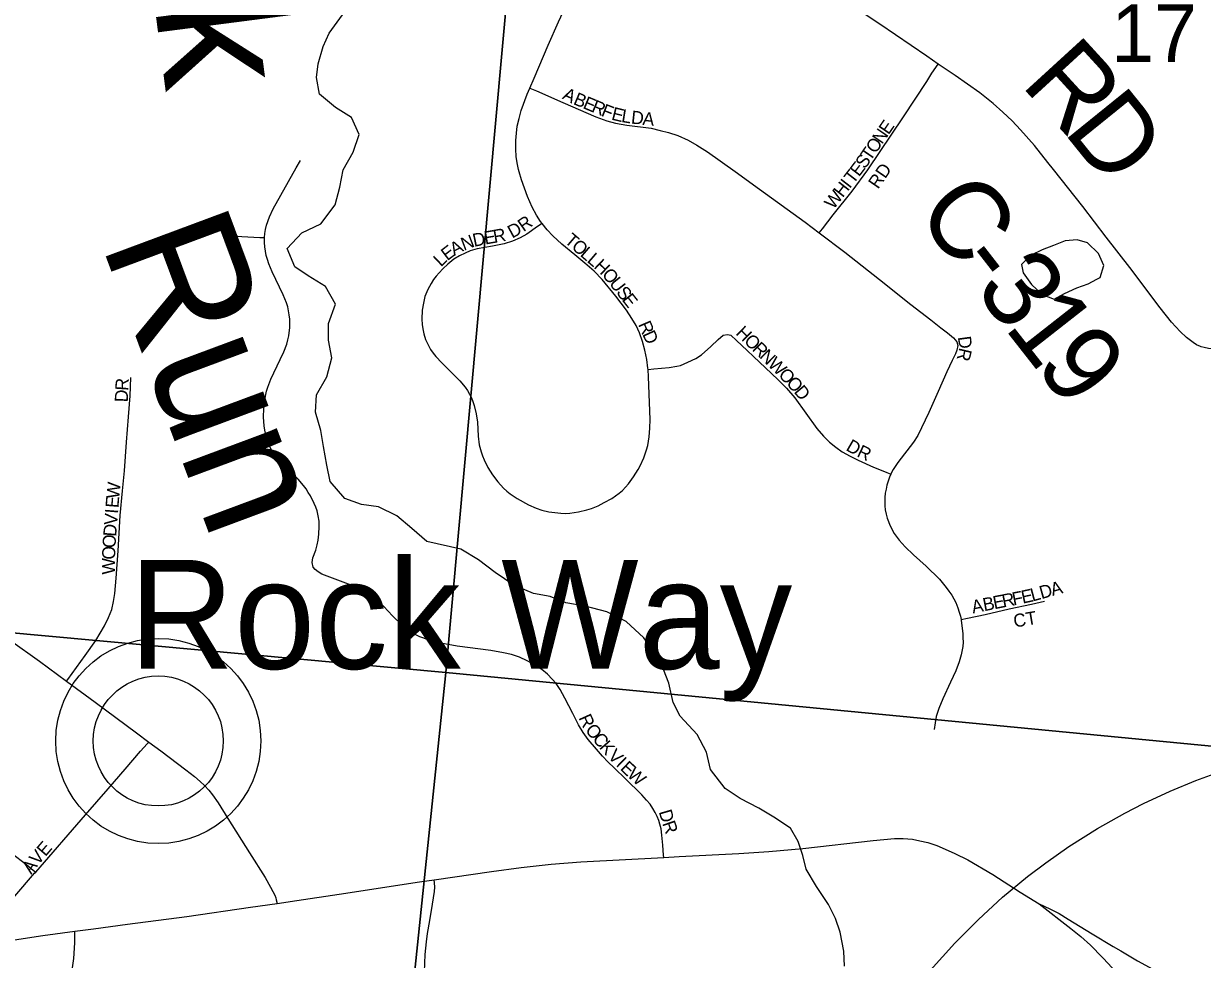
# Model space of a CAD drawing. Extents: x 1410790 to 1770854, y 566777 to 831614.
# Drawn here: x 1581361 to 1585877, y 704158 to 707743 of the extents above; entities that cross this region are included whole.
import ezdxf

# ---------------------------------------------------------------- set-up
doc = ezdxf.new("R2010")
doc.units = 0
for name, color, linetype in [('GM_X_County_Road', 7, 'Continuous'), ('GM_X_County_Road_Text', 7, 'Continuous'), ('GM_X_Minor_Lake', 7, 'Continuous'), ('GM_X_Minor_River', 7, 'Continuous'), ('GM_X_Minor_River_Text', 7, 'Continuous'), ('GM_X_Rail_Line', 7, 'Continuous'), ('GM_X_Section', 7, 'Continuous'), ('GM_X_Section_Text', 7, 'Continuous'), ('GM_X_Township_Road', 7, 'Continuous'), ('GM_X_Township_Subdivision', 7, 'Continuous'), ('GM_X_Township_Subdivision_Text', 7, 'Continuous'), ('GM_X_Unincorporated', 7, 'Continuous'), ('GM_X_Unincorporated_Location', 7, 'Continuous'), ('GM_X_Unincorporated_Text', 7, 'Continuous'), ('GM_X_US_Route', 7, 'Continuous')]:
    doc.layers.add(name, color=color, linetype=linetype)

msp = doc.modelspace()

# ---------------------------------------------------------------- linework, layer by layer
at = {"layer": 'GM_X_County_Road'}
for points in [[(1584864.9, 707588), (1584821.5, 707617.9), (1584640.9, 707741), (1584482.9, 707846.1), (1584384.8, 707911.1), (1584248.4, 707999.9), (1584099.2, 708099.5), (1583987.3, 708174.2), (1583765.5, 708320.1)], [(1585284.6, 707211.2), (1585232.9, 707275.8), (1585180, 707335.6), (1585148.2, 707370), (1585112.5, 707404.2), (1585075.1, 707436.5), (1585023.3, 707477.1), (1584929.6, 707543.5), (1584864.9, 707588)], [(1586504.2, 706606.8), (1586442.1, 706593.4), (1586173, 706537), (1586107.8, 706523.9), (1586043.8, 706510.5), (1585979.6, 706499), (1585947.5, 706496), (1585915.4, 706496.7), (1585899.5, 706498.7), (1585883.8, 706501.7), (1585872.2, 706505.2), (1585868.7, 706506.3), (1585854.4, 706512.6), (1585840.9, 706520.8), (1585815.4, 706540.6), (1585791.7, 706562.8), (1585758.7, 706598.7), (1585714.7, 706654.2), (1585598.5, 706808.4), (1585507.2, 706925), (1585418.7, 707042.2), (1585306.7, 707183.7), (1585284.6, 707211.2)], [(1581204.4, 705424.3), (1581219.9, 705420.6), (1581242.4, 705413.7), (1581264.6, 705404.9), (1581286.2, 705394.8), (1581310.9, 705379.8), (1581422.2, 705300.9), (1581491, 705249.3), (1581525.2, 705224.2)], [(1581525.2, 705224.2), (1581635.6, 705143.3), (1581793.2, 705026.1), (1581840.5, 704990.9)], [(1581840.5, 704990.9), (1581886.1, 704957), (1581982, 704884.3), (1582015.6, 704858.5), (1582036.9, 704839.9), (1582053.5, 704824.2), (1582070.1, 704806.6), (1582084.8, 704788.6), (1582106, 704758.3), (1582143.6, 704698), (1582226.4, 704566.5), (1582286.1, 704471.6), (1582306.7, 704435), (1582315.6, 704418.6), (1582323, 704403.8), (1582326.6, 704393.9), (1582328.5, 704386.1), (1582331.8, 704372.7)]]:
    msp.add_lwpolyline(points, dxfattribs=at)
at = {"layer": 'GM_X_Minor_Lake'}
for points in [[(1585472.4, 706763.4), (1585485.1, 706769.9), (1585499.5, 706815.9), (1585477.9, 706862.2), (1585436.3, 706902.6), (1585396.4, 706914.9), (1585350.4, 706911.2), (1585306.3, 706893.5), (1585262.3, 706875.8), (1585220.2, 706856), (1585183.9, 706820.2)], [(1585183.9, 706820.2), (1585189.7, 706788.1), (1585221.3, 706743.8), (1585262.9, 706705.4), (1585308.7, 706687), (1585348.8, 706708.8), (1585395, 706730.5), (1585439, 706746.2), (1585472.4, 706763.4)]]:
    msp.add_lwpolyline(points, dxfattribs=at)
at = {"layer": 'GM_X_Minor_River'}
for points in [[(1582905.6, 705759.4), (1582848.2, 705808.2), (1582790.6, 705857.1), (1582720.9, 705892), (1582654.8, 705900.8), (1582590.9, 705923.7), (1582535.6, 705988.5), (1582522.3, 706050.9), (1582509.2, 706123.3), (1582499.9, 706183.6), (1582478.8, 706254.1), (1582483.6, 706320.3), (1582522.6, 706390.1), (1582541.6, 706462.1), (1582528.4, 706530.5), (1582529.2, 706594.7), (1582556.2, 706668.7), (1582516.9, 706735.4), (1582451.3, 706776.3), (1582399.6, 706811), (1582370.4, 706881.6), (1582427.3, 706941.2), (1582499.9, 706976.4), (1582555, 707048.1), (1582571.9, 707116.1), (1582584.8, 707182.2), (1582623.8, 707250), (1582646.7, 707318), (1582617.4, 707382.6), (1582555.7, 707421.4), (1582494.2, 707472.3), (1582483, 707536.7), (1582489.7, 707588.8), (1582508.6, 707654.8), (1582531.3, 707706.8), (1582582.3, 707776.4)], [(1584505.9, 704132.1), (1584502.4, 704190.2), (1584488.9, 704262.4), (1584471.3, 704314.7), (1584443.8, 704368.9), (1584398.4, 704437.4), (1584359, 704503.8), (1584345.4, 704556), (1584327.8, 704610.2), (1584298.2, 704660.5), (1584234.7, 704703), (1584177, 704737.5), (1584105.4, 704774.1), (1584047.8, 704812.6), (1583992.4, 704885.1), (1583976.9, 704951.4), (1583941.5, 705019.7), (1583876.1, 705090.3), (1583848.6, 705142.7), (1583833.2, 705216.9), (1583811.6, 705269.2), (1583784.1, 705325.5), (1583736.6, 705389.9), (1583669.2, 705452.5), (1583595.6, 705489.2), (1583511.9, 705511.8), (1583438.1, 705524.4), (1583378.3, 705548.9), (1583314.5, 705559.3), (1583238.9, 705592), (1583167.3, 705640.6), (1583103.8, 705689.2), (1583036.2, 705729.7), (1582905.6, 705759.4)]]:
    msp.add_lwpolyline(points, dxfattribs=at)
at = {"layer": 'GM_X_Rail_Line'}
msp.add_lwpolyline([(1584833.4, 704115.1), (1584928.3, 704220.1), (1585018.4, 704311.1), (1585110.7, 704397.1), (1585205.9, 704476.1), (1585276.2, 704528.7), (1585364.3, 704591), (1585474.3, 704659.5), (1585578.8, 704717.7), (1585651, 704754.9), (1585753.4, 704803.1), (1585850.9, 704843), (1585949, 704879.4)], dxfattribs=at)
at = {"layer": 'GM_X_Section'}
for points in [[(1577923.7, 711041.4), (1583457.2, 710550.8), (1582978.6, 705257), (1577466, 705761.9)], [(1583457.2, 710550.8), (1588736.5, 710042.5), (1588248, 704750.8), (1582978.6, 705257)], [(1577466, 705761.9), (1582978.6, 705257), (1582419.4, 699882.5), (1577021.1, 700282.3)], [(1582978.6, 705257), (1588248, 704750.8), (1587775.4, 699456.9), (1582419.4, 699882.5)]]:
    msp.add_lwpolyline(points, close=True, dxfattribs=at)
at = {"layer": 'GM_X_Township_Road'}
msp.add_lwpolyline([(1582878.8, 703621.9), (1582880.5, 703666.5), (1582884, 703757.4), (1582887.5, 703849.7), (1582893.9, 704044.6), (1582899.4, 704176.5), (1582903.9, 704225.6), (1582908.4, 704258), (1582916.6, 704307.2), (1582927.5, 704369.2), (1582935, 704418.1), (1582936.3, 704434.9), (1582934.8, 704451.7), (1582933.8, 704463)], dxfattribs=at)
at = {"layer": 'GM_X_Township_Subdivision'}
for points in [[(1583300.4, 707496.2), (1583316.5, 707534.1), (1583370.1, 707660.8), (1583410, 707750), (1583444.8, 707823.9), (1583470.3, 707872.4), (1583513.7, 707937.8), (1583566.4, 708018.6), (1583610.5, 708086.5), (1583675.1, 708183.4), (1583741.4, 708283.7), (1583765.5, 708320.1)], [(1584408.9, 706941.7), (1584421.1, 706957.1), (1584462.7, 707009.8), (1584535, 707101.6), (1584595.4, 707182.4), (1584731.4, 707385.6), (1584820.6, 707521.6), (1584840.2, 707553), (1584864.9, 707588)], [(1583256.7, 707184.1), (1583252.8, 707202.7), (1583247.7, 707232.5), (1583246, 707263.1), (1583246.8, 707294.5), (1583248.5, 707322.6), (1583251.9, 707349.8), (1583258.7, 707379.5), (1583267.2, 707410.1), (1583290.2, 707472.1), (1583300.4, 707496.2)], [(1583300.4, 707496.2), (1583325.8, 707485.1), (1583426.5, 707440.8), (1583552.4, 707386.1), (1583594.9, 707370.5), (1583627.9, 707361.8), (1583671.3, 707354), (1583765, 707342.7), (1583798.9, 707334), (1583831, 707326.2), (1583866.6, 707314), (1583906.5, 707295.8), (1583939.5, 707277.6), (1583980.3, 707251.5), (1584087.1, 707176), (1584180, 707109.2), (1584355.3, 706982.4), (1584408.9, 706941.7)], [(1582283.6, 706923.4), (1582284.8, 706938.3), (1582287.5, 706954.8), (1582291.5, 706971.2), (1582302.7, 707002.6), (1582316.6, 707032.7), (1582405.3, 707190), (1582421.5, 707218.4)], [(1583347.1, 706977.7), (1583341.2, 706985.2), (1583325.9, 707009), (1583309.7, 707039.6), (1583291.8, 707080.6), (1583268.1, 707144.9), (1583258.7, 707174.7), (1583256.7, 707184.1)], [(1583347.1, 706977.7), (1583330.1, 706965.6), (1583289.3, 706936.7), (1583263, 706922.3), (1583233.2, 706909.5), (1583201.8, 706899.3), (1583156.7, 706890.8), (1583098.9, 706879.8), (1583071.8, 706872.1), (1583052.2, 706863.6), (1583031, 706853.4), (1583008.9, 706840.7), (1582985.9, 706822), (1582967.2, 706803.3), (1582952.9, 706787.6), (1582940.9, 706775.3), (1582931.5, 706762.5), (1582922.2, 706747.2), (1582909.4, 706724.3), (1582898.4, 706697.9), (1582892.4, 706672.4), (1582887.4, 706645.2), (1582886.5, 706611.3), (1582888.2, 706590), (1582890.7, 706573.8), (1582894.1, 706555.1), (1582900.9, 706532.2), (1582912.3, 706509.2), (1582920.1, 706494.2), (1582929.3, 706480.1), (1582939.8, 706467.1), (1582962.7, 706443.3), (1582998, 706409.5), (1583031.9, 706374.7), (1583052.6, 706350.5), (1583061.6, 706337.5), (1583069.4, 706323.8), (1583076.2, 706309.5), (1583082, 706294.7), (1583087, 706279.6), (1583094.2, 706248.3), (1583099.2, 706216.3), (1583102.3, 706162.5), (1583106.6, 706129.4), (1583113.4, 706102.8), (1583118.5, 706086.9), (1583124.7, 706071.5), (1583139.3, 706042.1), (1583156.8, 706014), (1583177, 705987.9), (1583199.5, 705963.7), (1583211.7, 705952.4), (1583224.6, 705941.9), (1583252.1, 705923.5), (1583295, 705899.1), (1583325, 705886.4), (1583346.2, 705879.5), (1583373.5, 705873), (1583419.5, 705867.4)], [(1583753.1, 706418.3), (1583752.7, 706423.1), (1583747.8, 706456), (1583740.6, 706492.3), (1583732.1, 706524.6), (1583720.2, 706558.6), (1583707.4, 706585.8), (1583690.4, 706613), (1583670, 706645.2), (1583629.2, 706698.8), (1583577.4, 706762.5), (1583546.8, 706794.8), (1583510.8, 706825.5), (1583472.6, 706856.9), (1583422.8, 706897.6), (1583388.7, 706929.9), (1583366.6, 706952.9), (1583347.1, 706977.7)], [(1582150.3, 706931.7), (1582197, 706926.9), (1582265.5, 706924.1), (1582283.6, 706923.4)], [(1583812.9, 704549.1), (1583812.4, 704557.8), (1583810.1, 704595.5), (1583806.2, 704633.9), (1583802.8, 704657.9), (1583797.9, 704676.2), (1583793.7, 704690.3), (1583787.6, 704705.9), (1583780.8, 704721.5), (1583771.9, 704735.9), (1583761.1, 704752.3), (1583747.6, 704768.7), (1583729.1, 704788.4), (1583707.1, 704809.9), (1583687, 704830), (1583668.2, 704849), (1583623.4, 704891.4), (1583600.4, 704914.3), (1583578.3, 704937.3), (1583554.9, 704963), (1583523.1, 705001), (1583504, 705027.9), (1583486.9, 705056.3), (1583464.7, 705100.5), (1583434.6, 705159.4), (1583416.7, 705191.8), (1583401.1, 705215.4), (1583385.9, 705232.1), (1583368, 705250.4), (1583345.7, 705269), (1583318.6, 705286.4), (1583290.1, 705302), (1583260.8, 705315.4), (1583230.3, 705325.5), (1583198.9, 705332.9), (1583150.8, 705340.9), (1583021.2, 705358.1), (1582972.9, 705366.7), (1582940.7, 705373.9), (1582908.9, 705382.9), (1582893.5, 705388.1), (1582878.4, 705394.1), (1582863.5, 705401.1), (1582849, 705409.4), (1582835.1, 705418.7), (1582809.4, 705439.8), (1582773.6, 705473.9), (1582740.3, 705509.9), (1582717.6, 705532.9), (1582705.6, 705543.5), (1582692.8, 705553.2), (1582679.5, 705562), (1582665.5, 705569.9), (1582636.2, 705583.5), (1582575.5, 705607.4), (1582513.8, 705629.6), (1582502.9, 705634.3), (1582489.5, 705642.2), (1582478.1, 705651.4), (1582469.7, 705660.9), (1582466, 705678.6), (1582469.1, 705696), (1582480.4, 705726.4), (1582485.7, 705746.6), (1582489.2, 705764.5), (1582492.2, 705786.5), (1582493.3, 705815.9), (1582492.6, 705837.2), (1582489.9, 705857), (1582485.3, 705876.1), (1582480.6, 705889.9), (1582474.2, 705905), (1582459.7, 705933.3), (1582451.7, 705947.1), (1582442.9, 705960.6), (1582433.4, 705973.6), (1582412.5, 705998.1), (1582389.6, 706020.6), (1582365.1, 706042.5), (1582353.1, 706053.9), (1582330.9, 706079.1), (1582321, 706092.7), (1582312.1, 706107), (1582304.2, 706121.9), (1582297.6, 706137.4), (1582292.4, 706153.3), (1582285.1, 706185.9), (1582282.6, 706202.3), (1582280.5, 706235.6), (1582281.6, 706268.8), (1582285.3, 706301.8), (1582291.8, 706334.5), (1582296.5, 706350.5), (1582308.5, 706381.4), (1582343.8, 706455.7), (1582357.5, 706485.2), (1582368.9, 706515.4), (1582373.3, 706530.9), (1582376.6, 706546.7), (1582380.2, 706578.6), (1582380.2, 706610.9), (1582378.7, 706626.9), (1582376.3, 706642.8), (1582372.6, 706658.4), (1582367.7, 706673.7), (1582355.2, 706703.5), (1582312.8, 706792.5), (1582300.1, 706823.1), (1582294.7, 706838.9), (1582290.5, 706855.1), (1582287.2, 706871.5), (1582284.9, 706888), (1582283.7, 706904.7), (1582283.6, 706911.9), (1582283.5, 706921.5), (1582283.6, 706923.4)], [(1584408.9, 706941.7), (1584507.2, 706867), (1584640, 706762), (1584759.8, 706666.5), (1584835.7, 706608), (1584874.4, 706578), (1584899.6, 706558.9), (1584923, 706538.9), (1584935.2, 706524.1), (1584939.5, 706510.2), (1584936, 706492), (1584930.9, 706478.1), (1584917.8, 706452.1), (1584897, 706408.7), (1584864, 706334), (1584828.8, 706253.4), (1584800.9, 706193.8), (1584785.8, 706165.3), (1584769.3, 706139.1), (1584709.6, 706062.2), (1584692.2, 706035), (1584684.8, 706020.8), (1584682.9, 706016.6)], [(1583753.1, 706418.3), (1583774.6, 706420), (1583834, 706424.9), (1583863.3, 706430.1), (1583876.8, 706433.8), (1583891.1, 706439), (1583906, 706445.5), (1583935.6, 706460.6), (1583958.1, 706474.4), (1583993.8, 706505.9), (1584021.9, 706533.1), (1584040.6, 706549.2), (1584057.6, 706551.8), (1584069.5, 706549.2), (1584092.4, 706528.8), (1584132.9, 706490.5), (1584156.3, 706467.9), (1584179.8, 706445.8), (1584203.3, 706423.9), (1584250, 706379.7), (1584282.8, 706346.9), (1584315.1, 706309.5), (1584400, 706192.3), (1584425.5, 706162.5), (1584448.5, 706139.6), (1584472.3, 706120), (1584496.9, 706103), (1584526.7, 706086.1), (1584557.3, 706070.8), (1584616.7, 706043.6), (1584658.4, 706026.6), (1584682.9, 706016.6)], [(1581525.2, 705224.2), (1581530.1, 705230.8), (1581597.2, 705321.9), (1581638.1, 705379.8), (1581671.2, 705436.2), (1581686.1, 705467.3), (1581698.8, 705498.3), (1581705.8, 705529.3), (1581710.1, 705559.7), (1581715, 705619), (1581722.8, 705723.4), (1581731.2, 705858.2), (1581739.7, 705953.4), (1581747.5, 706029.6), (1581755.2, 706139), (1581762.3, 706236.4), (1581769.3, 706317.6), (1581772.2, 706387.4)], [(1583419.5, 705867.4), (1583436.5, 705866.7), (1583453.2, 705867.6), (1583486.1, 705872.3), (1583518.8, 705880.1), (1583536, 705885.6), (1583561.7, 705895.7), (1583584.9, 705907.9), (1583614, 705923.7), (1583641.9, 705944.1), (1583654.8, 705955), (1583666.6, 705967), (1583677.5, 705979.7), (1583697.4, 706006.2), (1583715.2, 706034.3), (1583722.9, 706049.2), (1583736.3, 706079.5), (1583747.6, 706110.6), (1583752, 706126.7), (1583755.3, 706143.1), (1583757.6, 706159.6), (1583760.1, 706192.7), (1583760.5, 706225.8), (1583758.1, 706291.6), (1583755, 706390.1), (1583753.1, 706418.3)], [(1584682.9, 706016.6), (1584678.3, 706006), (1584668.2, 705975.4), (1584664.6, 705959.7), (1584661.9, 705943.8), (1584660.3, 705927.8), (1584659.6, 705911.8), (1584660.1, 705895.7), (1584661.9, 705879.9), (1584665, 705864.2), (1584669.3, 705848.8), (1584681, 705818.8), (1584695.8, 705790.1), (1584714.7, 705763.7), (1584737.3, 705738.5), (1584769.4, 705708.1), (1584818, 705663.9), (1584869.2, 705614.4), (1584894.4, 705583.1), (1584904.8, 705568.4), (1584916.1, 705552.8), (1584931.7, 705525), (1584939.3, 705504.7), (1584945, 705488.8), (1584949.4, 705472.6), (1584951.9, 705459.6)], [(1584951.9, 705459.6), (1584976.8, 705465.1), (1585044.6, 705479.9), (1585136.6, 705500.7), (1585221.6, 705518.9), (1585272, 705530.2)], [(1584951.9, 705459.6), (1584952.6, 705456.1), (1584958.2, 705407), (1584959.4, 705390.6), (1584959.5, 705373.9), (1584958.2, 705357.3), (1584952.3, 705324.4), (1584944.7, 705298.4), (1584931.7, 705263.7), (1584911.7, 705220.3), (1584882.2, 705156.9), (1584866.6, 705119.6), (1584857.1, 705088.4), (1584852.7, 705064), (1584849, 705038.7)], [(1581407.3, 704492.9), (1581598.5, 704711.9), (1581685.3, 704811.5), (1581749.9, 704886.7), (1581809, 704955.4), (1581834.7, 704984.3), (1581840.5, 704990.9)], [(1580839.3, 704937.3), (1580863.5, 704918.2), (1580914.7, 704877.7), (1581016.8, 704796.8), (1581107.2, 704727.3), (1581210.7, 704647.9), (1581312.8, 704566.8), (1581373.1, 704520.3), (1581397.9, 704500.5), (1581407.3, 704492.9)], [(1581200.2, 704214.5), (1581210.7, 704244), (1581219.3, 704262.5), (1581232.9, 704286.5), (1581274.2, 704337.8), (1581327.5, 704400.8), (1581403.1, 704488.1), (1581407.3, 704492.9)], [(1581437.2, 703181.3), (1581444.7, 703224.2), (1581451.8, 703273.9), (1581456.8, 703320.4), (1581463.1, 703396.3), (1581475.8, 703524.2), (1581489.6, 703657.7), (1581506.4, 703805.8), (1581518.1, 703913), (1581528.1, 703989.4), (1581539.9, 704064.9), (1581553.3, 704162.1), (1581557, 704222), (1581557.4, 704233.6), (1581557.1, 704247.7), (1581556.7, 704265.8)]]:
    msp.add_lwpolyline(points, dxfattribs=at)
at = {"layer": 'GM_X_Unincorporated'}
for radius in [392.8, 249]:
    msp.add_circle((1581877, 704994.8), radius, dxfattribs=at)
at = {"layer": 'GM_X_Unincorporated_Location'}
msp.add_line((1581877, 704994.8), (1581877, 704994.8), dxfattribs=at)
at = {"layer": 'GM_X_US_Route'}
for points in [[(1581200.2, 704214.5), (1581434.1, 704249.1), (1581556.7, 704265.8), (1581629.2, 704275.8), (1581759.1, 704293.1), (1581986.3, 704322.9), (1582229.6, 704357.9), (1582331.8, 704372.7), (1582408, 704383.8), (1582569.8, 704408.1), (1582877.7, 704454.8), (1582933.8, 704463), (1583153.3, 704495.3), (1583267.1, 704510.6), (1583381.3, 704522.8), (1583495.8, 704531.7), (1583812.9, 704549.1), (1583872.2, 704552.4), (1584101.2, 704563.9), (1584215.6, 704571.3), (1584346, 704583.3), (1584615.9, 704614.2), (1584697.4, 704621.3), (1584730.4, 704621.3), (1584765.4, 704618.1), (1584794.5, 704612.9), (1584824.3, 704605.8), (1584858.6, 704594.2), (1584891.6, 704580.6), (1584927.8, 704564.4), (1584977.7, 704539.1), (1585074.1, 704482.8), (1585178.9, 704416.1), (1585250.8, 704371.5)], [(1585250.8, 704371.5), (1585372, 704276.6), (1585410.4, 704245.5), (1585447.3, 704212.6), (1585494, 704166), (1585517.1, 704140.7), (1585538.4, 704117.3), (1585559.9, 704092.4), (1585601.6, 704044.1), (1585612.7, 704031.2), (1585618, 704025.1), (1585651.6, 703989.8), (1585675.4, 703966.9), (1585697, 703949.6), (1585710, 703940), (1585723.3, 703930.4), (1585737.5, 703922.1), (1585752.3, 703915), (1585783.4, 703903.9), (1585815.3, 703895.5), (1585847.8, 703889.8), (1585876.7, 703886.9)], [(1585250.8, 704371.5), (1585291.9, 704352.3), (1585327.3, 704334), (1585361.8, 704312), (1585454, 704255.6), (1585535.2, 704207.4), (1585564, 704190.4), (1585628.1, 704152.4), (1585686.6, 704121), (1585731.4, 704099.2), (1585762.2, 704086.8), (1585794, 704076.9), (1585821.4, 704070.7), (1585948.9, 704051.8)]]:
    msp.add_lwpolyline(points, dxfattribs=at)

# ---------------------------------------------------------------- texts
at = {"layer": 'GM_X_County_Road_Text'}
for s, rotation, p in [('R', 312.4491, (1585176.8, 707509.1)), ('D', 308.9534, (1585339.9, 707330.9)), ('C', 307.8418, (1584772.6, 707018)), ('-', 307.8699, (1584923.8, 706823.3)), ('3', 307.9095, (1584999.6, 706725.9)), ('1', 308.0964, (1585113.8, 706579.2)), ('9', 308.6654, (1585229.8, 706431.3))]:
    msp.add_text(s, height=300, rotation=rotation, dxfattribs=at).set_placement(p)
at = {"layer": 'GM_X_Minor_River_Text'}
for s, height, rotation, p in [('Rock', 500.55, 277.3727, (1581709.9, 708993)), ('Run', 500.33, 290.4322, (1581656.6, 706902.5))]:
    msp.add_text(s, height=height, rotation=rotation, dxfattribs=at).set_placement(p)
at = {"layer": 'GM_X_Section_Text'}
msp.add_text('17', height=221, rotation=0, dxfattribs=at).set_placement((1585527, 707595.6))
at = {"layer": 'GM_X_Township_Subdivision_Text'}
for s, rotation, p in [('A', 333.9823, (1583421.4, 707456)), ('B', 337.1055, (1583463.6, 707435.4)), ('E', 337.276, (1583500.2, 707420)), ('R', 337.302, (1583532.8, 707406.4)), ('F', 338.4905, (1583570.3, 707390.7)), ('E', 346.089, (1583610, 707375.6)), ('L', 350.8195, (1583648.6, 707366.2)), ('D', 354.0337, (1583686.3, 707360.2)), ('A', 354.2927, (1583730.3, 707355.5)), ('E', 55.6307, (1584674.1, 707314.6)), ('N', 55.6192, (1584649.2, 707278.3)), ('O', 55.6192, (1584624.4, 707242)), ('S', 54.6339, (1584583.6, 707183.5)), ('T', 55.5585, (1584604.4, 707212.9)), ('E', 52.5582, (1584561, 707153.9)), ('RD', 55.4801, (1584633.9, 707106.5)), ('I', 52.1496, (1584525.6, 707108.4)), ('T', 52.1466, (1584539.1, 707125.8)), ('W', 52.1516, (1584463.5, 707028.5)), ('H', 52.1423, (1584498.6, 707073.7)), ('D', 28.4352, (1583232.2, 706919.1)), ('R', 35.0961, (1583276.2, 706943.4)), ('N', 20.8681, (1583047.4, 706872.4)), ('D', 11.6872, (1583086.5, 706887.5)), ('E', 9.8307, (1583129.2, 706896.4)), ('R', 10.395, (1583164.4, 706902.5)), ('T', 319.292, (1583429.8, 706906.8)), ('E', 37.2688, (1582983.9, 706832.3)), ('A', 28.0802, (1583010.1, 706852.4)), ('O', 319.2924, (1583456.5, 706883.8)), ('L', 319.3004, (1583489.9, 706855.1)), ('L', 43.3193, (1582959.4, 706809)), ('L', 319.2742, (1583516.5, 706832.2)), ('H', 316.3912, (1583542.7, 706809.6)), ('O', 310.4353, (1583573.6, 706780.3)), ('U', 308.2297, (1583601.8, 706747.2)), ('S', 308.0068, (1583629, 706712.7)), ('E', 308.0348, (1583650.7, 706684.9)), ('R', 293.3708, (1583714, 706590.8)), ('D', 294.4415, (1583730.1, 706553.5)), ('H', 315.7264, (1584085.9, 706554.3)), ('O', 315.7482, (1584117.4, 706523.6)), ('R', 315.7213, (1584148.9, 706492.9)), ('D', 277.7622, (1584939.5, 706542.4)), ('N', 315.7482, (1584177.3, 706465.2)), ('W', 315.6063, (1584208.8, 706434.5)), ('R', 256.8179, (1584945.7, 706503.6)), ('R', 86.2328, (1581761.4, 706335.4)), ('O', 313.9955, (1584249.4, 706394.8)), ('O', 313.0059, (1584279.8, 706363.3)), ('D', 88.1637, (1581760, 706291.9)), ('D', 309.9707, (1584309.4, 706331.6)), ('D', 329.8946, (1584507.7, 706110.5)), ('R', 334.67, (1584549.7, 706086.4)), ('W', 84.2743, (1581726.9, 705920.9)), ('E', 85.4941, (1581724.2, 705886.1)), ('I', 85.4505, (1581722.4, 705864.1)), ('V', 85.4923, (1581719, 705820.2)), ('D', 85.4923, (1581715.5, 705776.4)), ('O', 86.0405, (1581712.5, 705732.6)), ('O', 88.8416, (1581711.6, 705689.3)), ('W', 89.9159, (1581711.6, 705632.3)), ('F', 11.1277, (1585152.6, 705513.7)), ('E', 12.0871, (1585188, 705520.7)), ('L', 14.9764, (1585225.1, 705528.7)), ('D', 15.6929, (1585259.8, 705538)), ('A', 15.7071, (1585302.2, 705549.9)), ('A', 11.1299, (1584997.2, 705483.2)), ('B', 11.1194, (1585040.3, 705491.7)), ('E', 11.1029, (1585079.2, 705499.3)), ('R', 11.1308, (1585113.7, 705506.1)), ('CT', 9.4682, (1585156.8, 705429.2)), ('R', 294.3053, (1583486, 705084)), ('O', 309.2006, (1583509.7, 705035.9)), ('C', 309.1339, (1583537.5, 705001.8)), ('K', 311.1778, (1583563.8, 704969.6)), ('V', 315.78, (1583595.8, 704933.3)), ('I', 316.2135, (1583627.6, 704902.3)), ('E', 316.1975, (1583643.5, 704887.1)), ('W', 317.5879, (1583669.9, 704861.8)), ('D', 286.3057, (1583793.6, 704724)), ('R', 288.8168, (1583806.7, 704679.6)), ('V', 49.6263, (1581416, 704516.3)), ('E', 49.4283, (1581444.5, 704549.8)), ('A', 53.1563, (1581390.1, 704481.7))]:
    msp.add_text(s, height=50, rotation=rotation, dxfattribs=at).set_placement(p)
at = {"layer": 'GM_X_Unincorporated_Text'}
msp.add_text('Rock Way', height=417, rotation=0, dxfattribs=at).set_placement((1581765, 705271.3))

doc.saveas('drawing.dxf')
